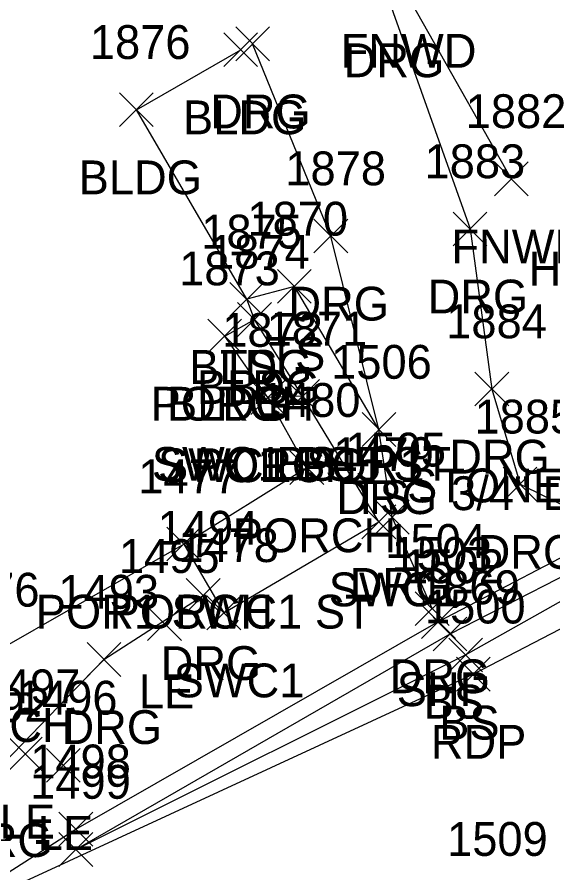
# Model space of a CAD drawing. Extents: x 1657482 to 1661439, y 647981 to 649041.
# Drawn here: x 1659950.7 to 1659982.3, y 648132.6 to 648183.2 of the extents above; entities that cross this region are included whole.
import ezdxf

# ---------------------------------------------------------------- set-up
doc = ezdxf.new("R2010")
doc.units = 0
for name, color, linetype in [('L_A', 7, 'Continuous'), ('L_C', 7, 'Continuous'), ('L_I', 7, 'Continuous'), ('L_TIC', 7, 'Continuous'), ('LBC', 7, 'Continuous'), ('LBF', 7, 'Continuous'), ('LELB', 7, 'Continuous'), ('LFNC', 7, 'Continuous'), ('M_C', 7, 'Continuous'), ('P_A', 7, 'Continuous'), ('P_I', 7, 'Continuous'), ('P_TIC', 7, 'Continuous'), ('PET', 7, 'Continuous'), ('PSP', 7, 'Continuous'), ('R_A', 7, 'Continuous'), ('R_I', 7, 'Continuous'), ('R_TIC', 7, 'Continuous'), ('RDG', 7, 'Continuous'), ('RSW', 7, 'Continuous')]:
    doc.layers.add(name, color=color, linetype=linetype)

msp = doc.modelspace()

# ---------------------------------------------------------------- linework, layer by layer
at = {"layer": 'L_TIC'}
for points in [[(1659962.885, 648180.264), (1659964.885, 648182.264)], [(1659964.885, 648180.264), (1659962.885, 648182.264)], [(1659956.719, 648176.716), (1659958.719, 648178.716)], [(1659958.719, 648176.716), (1659956.719, 648178.716)], [(1659978.879, 648172.629), (1659980.879, 648174.629)], [(1659980.879, 648172.629), (1659978.879, 648174.629)], [(1659966.061, 648166.274), (1659968.061, 648168.274)], [(1659968.061, 648166.274), (1659966.061, 648168.274)], [(1659963.249, 648165.509), (1659965.249, 648167.509)], [(1659965.249, 648165.509), (1659963.249, 648167.509)], [(1659963.249, 648165.509), (1659965.249, 648167.509)], [(1659965.249, 648165.509), (1659963.249, 648167.509)], [(1659963.704, 648164.315), (1659965.704, 648166.315)], [(1659965.704, 648164.315), (1659963.704, 648166.315)], [(1659963.704, 648164.315), (1659965.704, 648166.315)], [(1659965.704, 648164.315), (1659963.704, 648166.315)], [(1659961.943, 648163.333), (1659963.943, 648165.333)], [(1659963.943, 648163.333), (1659961.943, 648165.333)], [(1659961.943, 648163.333), (1659963.943, 648165.333)], [(1659963.943, 648163.333), (1659961.943, 648165.333)], [(1659964.489, 648159.698), (1659966.489, 648161.698)], [(1659966.489, 648159.698), (1659964.489, 648161.698)], [(1659966.542, 648159.775), (1659968.542, 648161.775)], [(1659968.542, 648159.775), (1659966.542, 648161.775)], [(1659971.058, 648157.809), (1659973.058, 648159.809)], [(1659973.058, 648157.809), (1659971.058, 648159.809)], [(1659966.795, 648155.554), (1659968.795, 648157.554)], [(1659968.795, 648155.554), (1659966.795, 648157.554)], [(1659959.522, 648151.038), (1659961.522, 648153.038)], [(1659961.522, 648151.038), (1659959.522, 648153.038)], [(1659958.379, 648146.327), (1659960.379, 648148.327)], [(1659960.379, 648146.327), (1659958.379, 648148.327)], [(1659975.261, 648145.72), (1659977.261, 648147.72)], [(1659977.261, 648145.72), (1659975.261, 648147.72)], [(1659976.18, 648144.48), (1659978.18, 648146.48)], [(1659978.18, 648144.48), (1659976.18, 648146.48)], [(1659976.18, 648144.48), (1659978.18, 648146.48)], [(1659978.18, 648144.48), (1659976.18, 648146.48)], [(1659950.153, 648138.624), (1659952.153, 648140.624)], [(1659952.153, 648138.624), (1659950.153, 648140.624)], [(1659952.403, 648137.953), (1659954.403, 648139.953)], [(1659954.403, 648137.953), (1659952.403, 648139.953)], [(1659953.142, 648132.978), (1659955.142, 648134.978)], [(1659955.142, 648132.978), (1659953.142, 648134.978)], [(1659953.142, 648132.978), (1659955.142, 648134.978)], [(1659955.142, 648132.978), (1659953.142, 648134.978)]]:
    msp.add_lwpolyline(points, dxfattribs=at)
at = {"layer": 'LBC'}
msp.add_lwpolyline([(1659962.943, 648164.333), (1659964.704, 648165.315), (1659964.249, 648166.509), (1659957.719, 648177.716), (1659963.885, 648181.264)], dxfattribs=at)
at = {"layer": 'LBF'}
msp.add_lwpolyline([(1659908.182, 648122.418), (1659908.18, 648122.094), (1659908.507, 648121.945), (1659924.538, 648131.214), (1659924.906, 648131.272), (1659937.92, 648138.97), (1659938.46, 648139.163), (1659940.383, 648140.382), (1659940.94, 648140.486), (1659948.795, 648145.337), (1659960.522, 648152.038), (1659967.795, 648156.554), (1659965.489, 648160.698), (1659962.943, 648164.333)], dxfattribs=at)
at = {"layer": 'LELB'}
for points in [[(1659972.058, 648158.809), (1659967.061, 648167.274), (1659964.249, 648166.509)], [(1659967.542, 648160.775), (1659964.704, 648165.315)], [(1659977.18, 648145.48), (1659987.077, 648151.074), (1659995.171, 648155.493), (1659998.959, 648158.076), (1660000.752, 648159.264), (1660001.377, 648159.909), (1660000.398, 648161.342), (1659998.852, 648160.64)], [(1659954.142, 648133.978), (1659976.261, 648146.72), (1659986.563, 648152.007), (1659994.698, 648156.61), (1659997.976, 648158.996), (1659999.124, 648159.54)], [(1659954.142, 648133.978), (1659977.18, 648145.48)]]:
    msp.add_lwpolyline(points, dxfattribs=at)
at = {"layer": 'LFNC'}
msp.add_lwpolyline([(1659973.335, 648185.198), (1659979.879, 648173.629)], dxfattribs=at)
at = {"layer": 'P_TIC'}
for points in [[(1659974.576, 648146.453), (1659976.576, 648148.453)], [(1659976.576, 648146.453), (1659974.576, 648148.453)], [(1659976.635, 648143.34), (1659978.635, 648145.34)], [(1659978.635, 648143.34), (1659976.635, 648145.34)], [(1659953.137, 648134.182), (1659955.137, 648136.182)], [(1659955.137, 648134.182), (1659953.137, 648136.182)]]:
    msp.add_lwpolyline(points, dxfattribs=at)
at = {"layer": 'PET'}
msp.add_lwpolyline([(1659797.957, 648111.988), (1659819.59, 648111.147), (1659820.376, 648114.717), (1659842.939, 648112.708), (1659860.056, 648111.284), (1659870.084, 648111.395), (1659880.312, 648111.43), (1659885.231, 648111.845), (1659895.84, 648113.342), (1659903.958, 648115.551), (1659911.843, 648118.071), (1659934.128, 648124.4), (1659939.783, 648126.971), (1659944.648, 648129.118), (1659977.635, 648144.34), (1659987.87, 648149.672), (1659995.671, 648153.846), (1660001.577, 648157.024), (1660026.061, 648170.189)], dxfattribs=at)
at = {"layer": 'PSP'}
msp.add_lwpolyline([(1659944.648, 648129.118), (1659954.137, 648135.182), (1659975.576, 648147.453), (1659985.92, 648152.856), (1659993.97, 648157.361), (1659997.725, 648159.549), (1659998.902, 648160.265), (1659999.124, 648159.54), (1659999.433, 648158.734), (1660000.752, 648159.264), (1660000.872, 648158.072), (1660001.577, 648157.024)], dxfattribs=at)
at = {"layer": 'R_TIC'}
for points in [[(1659963.591, 648180.612), (1659965.591, 648182.612)], [(1659965.591, 648180.612), (1659963.591, 648182.612)], [(1659976.444, 648169.669), (1659978.444, 648171.669)], [(1659978.444, 648169.669), (1659976.444, 648171.669)], [(1659968.217, 648169.249), (1659970.217, 648171.249)], [(1659970.217, 648169.249), (1659968.217, 648171.249)], [(1659977.725, 648160.202), (1659979.725, 648162.202)], [(1659979.725, 648160.202), (1659977.725, 648162.202)], [(1659964.489, 648159.698), (1659966.489, 648161.698)], [(1659966.489, 648159.698), (1659964.489, 648161.698)], [(1659966.542, 648159.775), (1659968.542, 648161.775)], [(1659968.542, 648159.775), (1659966.542, 648161.775)], [(1659971.058, 648157.809), (1659973.058, 648159.809)], [(1659973.058, 648157.809), (1659971.058, 648159.809)], [(1659979.398, 648154.573), (1659981.398, 648156.573)], [(1659981.398, 648154.573), (1659979.398, 648156.573)], [(1659971.055, 648152.354), (1659973.055, 648154.354)], [(1659973.055, 648152.354), (1659971.055, 648154.354)], [(1659971.844, 648152.623), (1659973.844, 648154.623)], [(1659973.844, 648152.623), (1659971.844, 648154.623)], [(1659959.522, 648151.038), (1659961.522, 648153.038)], [(1659961.522, 648151.038), (1659959.522, 648153.038)], [(1659960.667, 648147.999), (1659962.667, 648149.999)], [(1659962.667, 648147.999), (1659960.667, 648149.999)], [(1659974.205, 648147.217), (1659976.205, 648149.217)], [(1659976.205, 648147.217), (1659974.205, 648149.217)], [(1659961.887, 648146.972), (1659963.887, 648148.972)], [(1659963.887, 648146.972), (1659961.887, 648148.972)], [(1659954.805, 648144.214), (1659956.805, 648146.214)], [(1659956.805, 648144.214), (1659954.805, 648146.214)]]:
    msp.add_lwpolyline(points, dxfattribs=at)
at = {"layer": 'RDG'}
for points in [[(1659972.485, 648184.638), (1659977.444, 648170.669), (1659978.725, 648161.202), (1659980.398, 648155.573), (1659985.92, 648152.856)], [(1659975.205, 648148.217), (1659972.844, 648153.623), (1659972.058, 648158.809), (1659969.217, 648170.249), (1659964.591, 648181.612)], [(1659944.648, 648129.118), (1659949.336, 648138.531), (1659955.805, 648145.214), (1659961.667, 648148.999)]]:
    msp.add_lwpolyline(points, dxfattribs=at)
at = {"layer": 'RSW'}
msp.add_lwpolyline([(1659960.522, 648152.038), (1659962.887, 648147.972), (1659972.055, 648153.354), (1659967.542, 648160.775), (1659965.489, 648160.698)], dxfattribs=at)

# ---------------------------------------------------------------- texts
at = {"layer": 'L_A'}
for s, p in [('FNWD', (1659969.8, 648180.198)), ('BLDG', (1659960.476, 648176.264)), ('BLDG', (1659954.309, 648172.716)), ('FNWD', (1659976.343, 648168.629)), ('HEDGE', (1659980.91, 648167.315)), ('TS', (1659965.471, 648162.274)), ('BLDG', (1659960.84, 648161.509)), ('TS', (1659962.659, 648161.509)), ('BLDG', (1659961.295, 648160.315)), ('BS', (1659963.145, 648160.315)), ('PORCH', (1659958.565, 648159.333)), ('BLDG', (1659959.533, 648159.333)), ('BS', (1659965.983, 648155.775)), ('PORCH', (1659961.111, 648155.698)), ('TS', (1659970.468, 648153.809)), ('PORCH', (1659963.417, 648151.554)), ('PORCH', (1659956.144, 648147.038)), ('LE', (1659957.867, 648142.327)), ('BS', (1659974.702, 648141.72)), ('PORCH', (1659944.417, 648140.337)), ('BS', (1659975.621, 648140.48)), ('BS', (1659975.621, 648140.48)), ('LE', (1659949.642, 648134.624)), ('LE', (1659951.891, 648133.953))]:
    msp.add_text(s, height=2, dxfattribs=at).set_placement(p)
at = {"layer": 'L_C'}
msp.add_text('STONE RETAINING', height=2, dxfattribs=at).set_placement((1659973.723, 648154.501))
at = {"layer": 'L_I'}
for s, p in [('1876', (1659954.971, 648180.716)), ('1882', (1659977.186, 648176.629)), ('1870', (1659964.282, 648170.274)), ('1875', (1659961.556, 648169.509)), ('1875', (1659961.556, 648169.509)), ('1874', (1659962.011, 648168.315)), ('1874', (1659962.011, 648168.315)), ('1873', (1659960.25, 648167.333)), ('1873', (1659960.25, 648167.333)), ('1872', (1659962.796, 648163.698)), ('1871', (1659965.417, 648163.775)), ('1506', (1659969.232, 648161.809)), ('1480', (1659965.016, 648159.554)), ('1477', (1659957.829, 648155.038)), ('1495', (1659956.686, 648150.327)), ('1502', (1659973.49, 648149.72)), ('1476', (1659946.047, 648148.337)), ('1869', (1659974.432, 648148.48)), ('1869', (1659974.432, 648148.48)), ('1497', (1659948.461, 648142.624)), ('1496', (1659950.655, 648141.953)), ('1499', (1659951.442, 648136.978)), ('1499', (1659951.442, 648136.978))]:
    msp.add_text(s, height=2, dxfattribs=at).set_placement(p)
at = {"layer": 'M_C'}
msp.add_text('3/4" DOWN 2"', height=2, dxfattribs=at).set_placement((1659976.32, 648154.043))
at = {"layer": 'P_A'}
for s, p in [('SHP', (1659973.111, 648142.453)), ('RDP', (1659975.123, 648139.34))]:
    msp.add_text(s, height=2, dxfattribs=at).set_placement(p)
at = {"layer": 'P_I'}
for s, p in [('1503', (1659972.804, 648150.453)), ('1500', (1659974.777, 648147.34)), ('1498', (1659951.445, 648138.182)), ('1509', (1659976.086, 648133.6))]:
    msp.add_text(s, height=2, dxfattribs=at).set_placement(p)
at = {"layer": 'R_A'}
for s, p in [('DRG', (1659969.973, 648179.638)), ('DRG', (1659962.079, 648176.612)), ('DRG', (1659974.933, 648165.669)), ('DRG', (1659966.705, 648165.249)), ('SWC1 BS5 ST', (1659958.637, 648155.775)), ('DRG', (1659976.213, 648156.202)), ('SWC1 POR1', (1659959.001, 648155.698)), ('DRG', (1659969.546, 648153.809)), ('DRG', (1659977.886, 648150.573)), ('SWC1', (1659969.094, 648148.354)), ('DRG', (1659970.332, 648148.623)), ('POR1 SWC1 ST', (1659951.774, 648147.038)), ('DRG', (1659959.155, 648143.999)), ('DRG', (1659972.694, 648143.217)), ('SWC1', (1659959.927, 648142.972)), ('DRG', (1659953.293, 648140.214)), ('DRG', (1659946.825, 648133.531))]:
    msp.add_text(s, height=2, dxfattribs=at).set_placement(p)
at = {"layer": 'R_I'}
for s, p in [('1883', (1659974.752, 648173.669)), ('1878', (1659966.524, 648173.249)), ('1884', (1659976.032, 648164.202)), ('1872', (1659962.796, 648163.698)), ('1871', (1659965.417, 648163.775)), ('1506', (1659969.232, 648161.809)), ('1885', (1659977.705, 648158.573)), ('1479', (1659969.354, 648156.354)), ('1505', (1659970.072, 648156.623)), ('1477', (1659957.829, 648155.038)), ('1494', (1659958.974, 648151.999)), ('1504', (1659972.434, 648151.217)), ('1478', (1659960.195, 648150.972)), ('1493', (1659953.112, 648148.214)), ('1492', (1659946.644, 648141.531))]:
    msp.add_text(s, height=2, dxfattribs=at).set_placement(p)

doc.saveas('drawing.dxf')
